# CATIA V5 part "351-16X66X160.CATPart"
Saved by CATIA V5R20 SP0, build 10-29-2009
Part number: 351-16X66X160
Definition: NONE
Nomenclature: 351-16X66X160
Source: Unknown
Description: 351-16X66X160
Bounding box of the stored display mesh (mm): x -5 to 155, y -13 to 13, z -13 to 13
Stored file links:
  C:\Users\Utente\Desktop\IO LAVORO\3D X SITO CF\X SITO\PLASTICA\351\351-16X66X160.CATPart
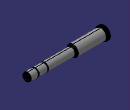
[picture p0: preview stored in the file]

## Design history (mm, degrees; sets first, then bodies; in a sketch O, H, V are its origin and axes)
Body1 "351-16X66X160" (main body)
  Solid1: solid without history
